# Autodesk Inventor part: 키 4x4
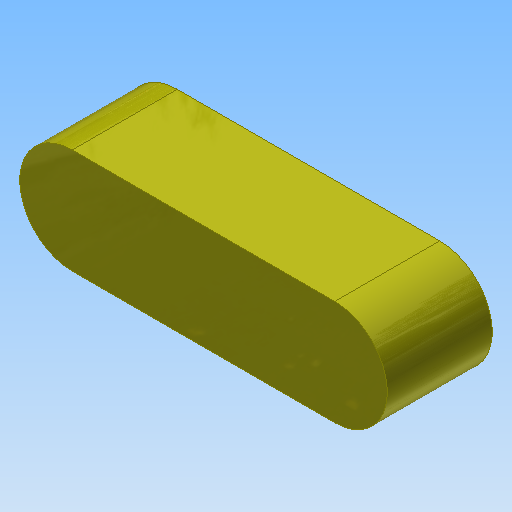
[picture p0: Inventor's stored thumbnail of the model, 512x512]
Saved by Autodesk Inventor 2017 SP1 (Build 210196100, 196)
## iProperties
Created: 2018-09
Part Number: 키 4x4
Document SubType Name: Modeling
Density: 7.86 g/cm^3
Material: 강철, 연강
Appearance: 노란색
Mass: 1.65269 g
Surface Area: 2.35398 cm^2
Volume: 0.210265 cm^3
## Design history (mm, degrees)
sketch "스케치1"
  geometry: L1 (-5, -2)-(5, -2); L2 (5, 2)-(-5, 2); A1 r 2 centre (5, 0) between (5, -2) and (5, 2); A2 r 2 centre (-5, 0) between (-5, 2) and (-5, -2); 2 further points
  constraints: 4 end point, 4 point on circle, 4 tangent, 2 centre point, 1 horizontal, 1 horizontal alignment, 1 midpoint, 1 parallel, 1 vertical alignment
  dimensions: "d0" = 4 distance between parallel lines of L1 L2; "d1" = 14 dimension on A1 A2
extrude "돌출1" new body sketch "스케치1" stored distance "d2" = 4; taper "d3" = 0 deg
node "솔리드1"
